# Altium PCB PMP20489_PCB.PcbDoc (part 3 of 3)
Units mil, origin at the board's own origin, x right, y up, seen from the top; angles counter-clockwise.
Board outline 4000 x 6000 mil, 8 copper layers (Top Layer, Signal Layer 1, Signal Layer 2, Signal Layer 3, Signal Layer 4, Signal Layer 5, Signal Layer 6, Bottom Layer), stack 63 mil thick; 331 components, 128 nets, 876 pads, 1027 vias.
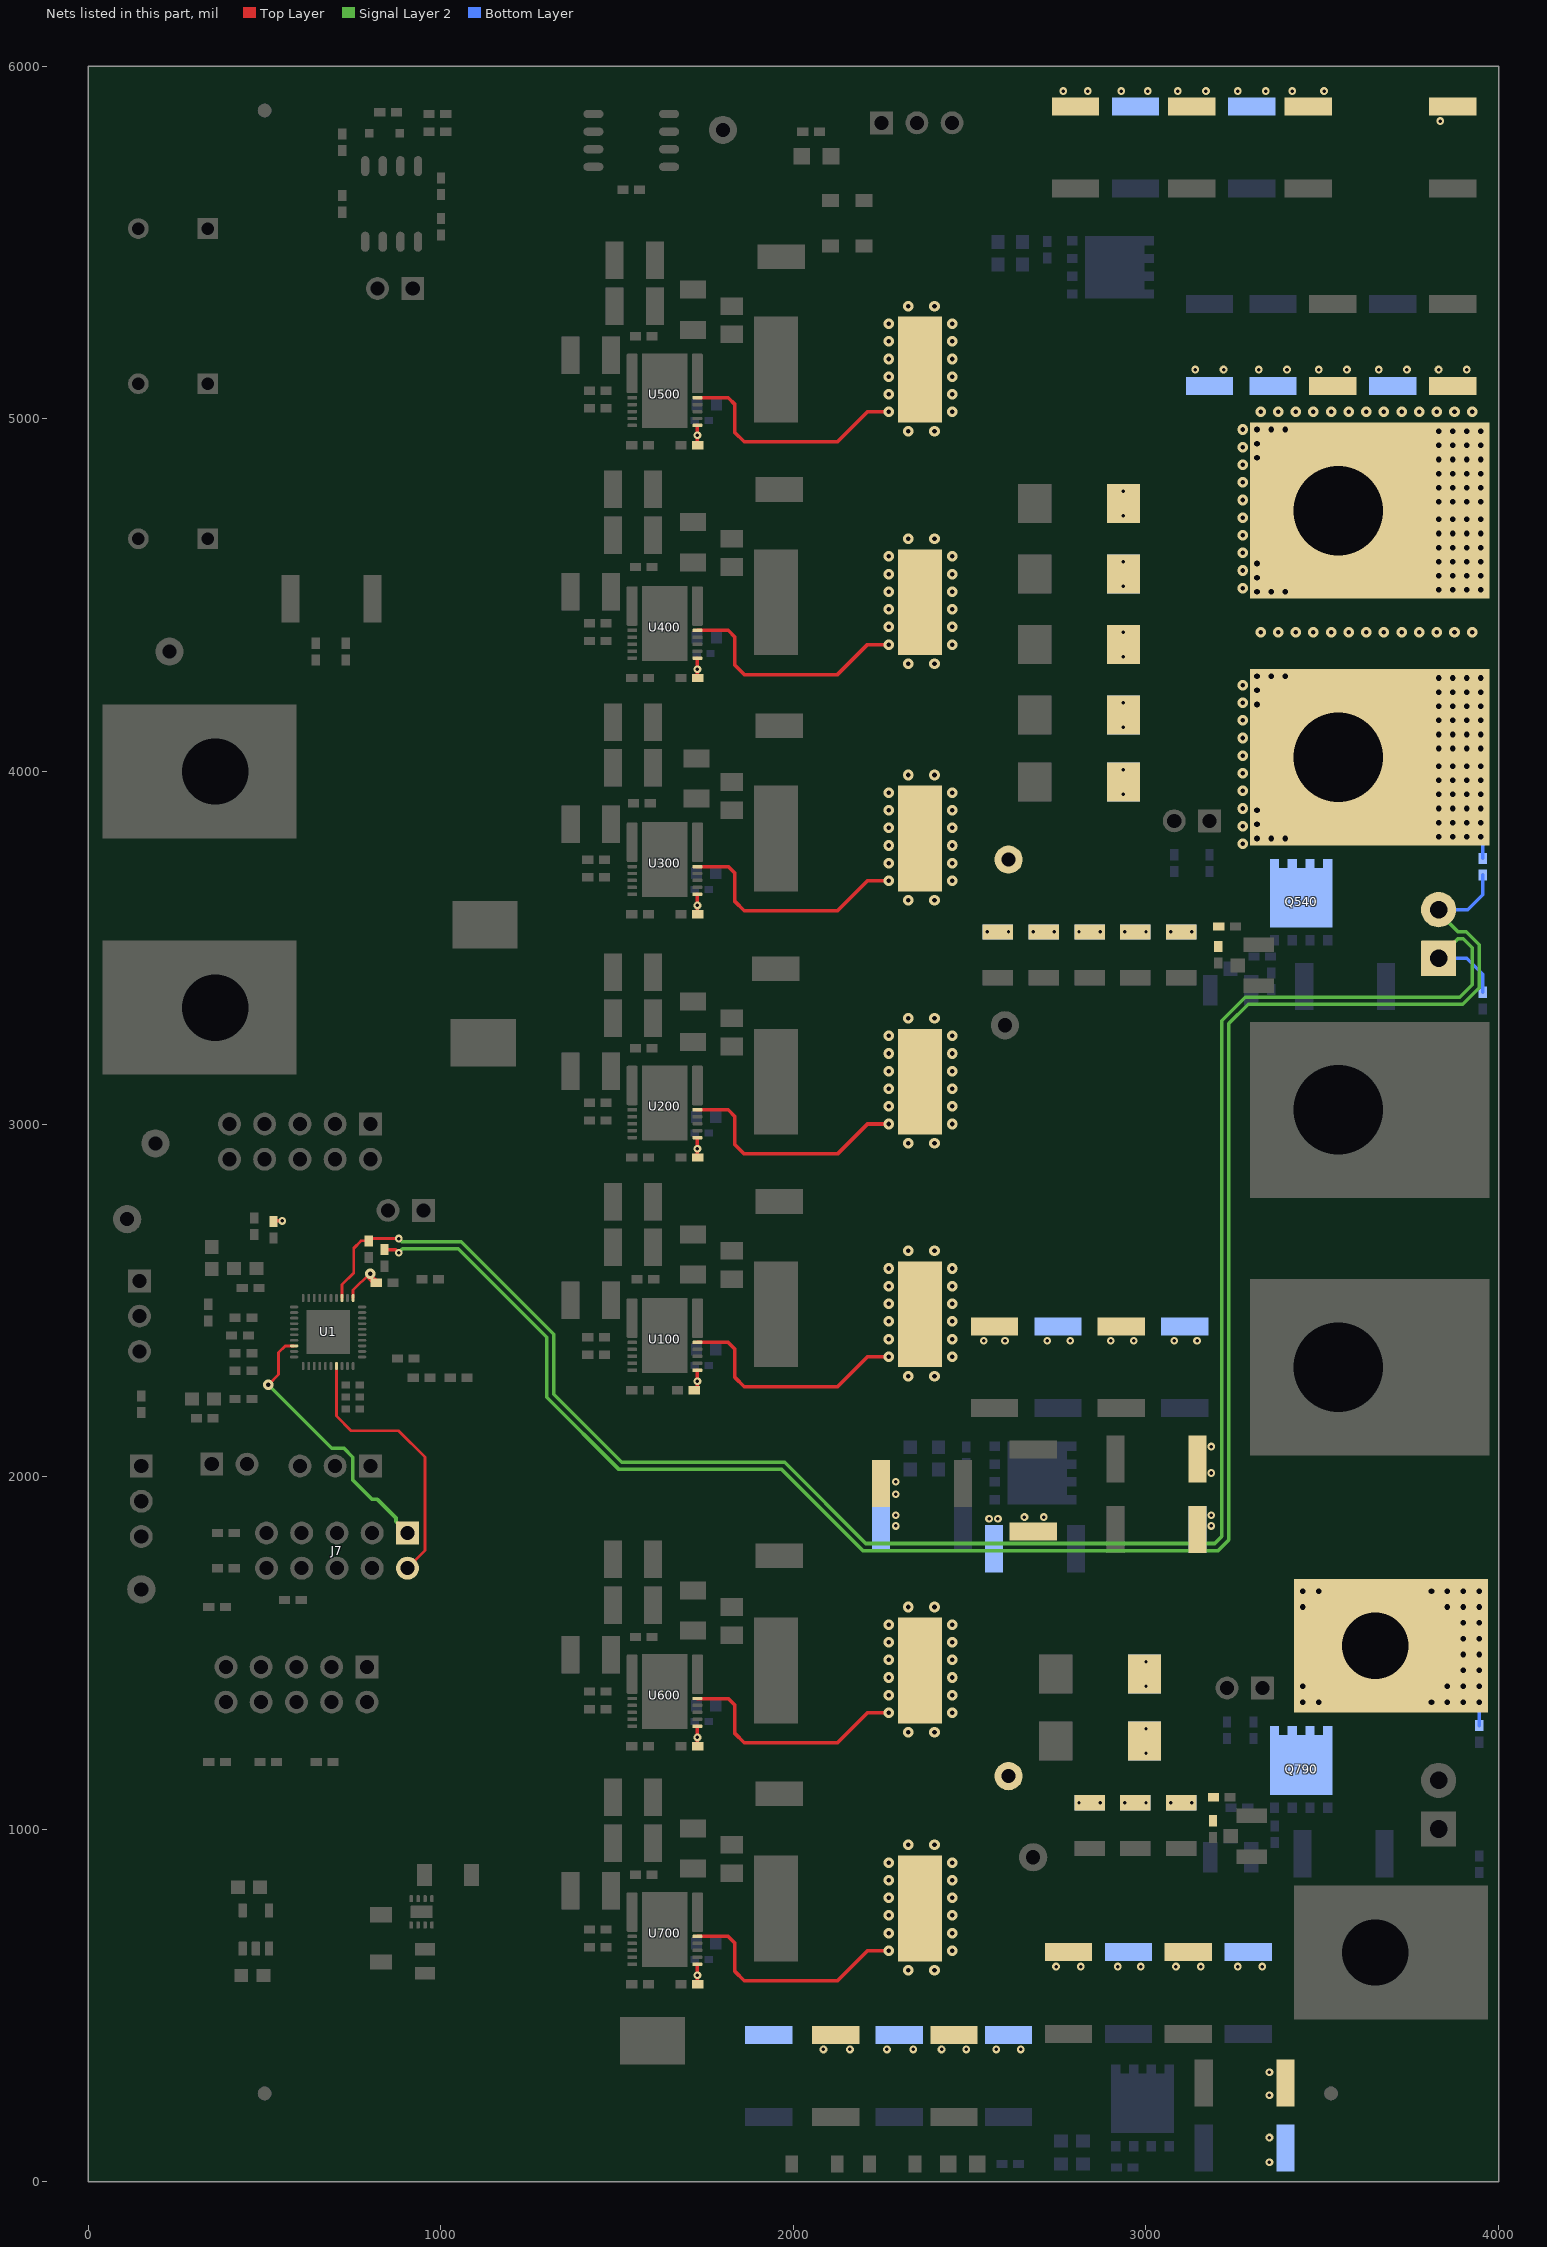
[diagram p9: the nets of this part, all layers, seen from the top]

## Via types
v1: diameter 32, hole 16, Top Layer to Bottom Layer, 344 vias
v2: diameter 22, hole 10, Top Layer to Bottom Layer, tented both sides, 216 vias
v3: diameter 30, hole 13, Top Layer to Bottom Layer, tented both sides, 211 vias
v4: diameter 22, hole 9.7, Top Layer to Bottom Layer, 144 vias
v5: diameter 19.68, hole 7.87, Top Layer to Bottom Layer, 112 vias

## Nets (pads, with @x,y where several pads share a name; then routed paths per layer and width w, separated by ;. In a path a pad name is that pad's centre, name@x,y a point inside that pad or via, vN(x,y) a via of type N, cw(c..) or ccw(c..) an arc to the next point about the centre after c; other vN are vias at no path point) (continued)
VOUT: C21.1 C22.1 C23.1 C24.1 C25.1 C26.1 C27.1 C28.1 C29.1 C30.1 C31.1 C32.1 C33.1 C34.1 C35.1 C36.1 C37.1 C38.1 C39.1 C40.1 C77.1 J15.1 J16.1 L100.2 L200.2 L300.2 L400.2 L500.2 Q540.5 Q540.6 Q540.7 Q540.8 Q540.9 R71.2 R77.2 R505.2 R506.2 R507.2 R508.2 R509.2 R511.2 R512.2 R514.2 R515.2 R525.2 R526.2 R527.2 R528.2 R529.2 R530.2 R531.2 R532.2 R533.2 R534.2 R535.2 R550.2 R553.2 U100.5 U200.5 U300.5 U400.5 U500.5 Vout.1 | length 3468.7
  Top Layer w10: U100.5@1727.52,2380.31 1814.69,2380.31 1834,2361 1834,2281 1860,2255 2125,2255 2210,2340 v3@2275,2340 ; U200.5@1727.52,3040.31 1814.69,3040.31 1834,3021 1834,2941 1860,2915 2125,2915 2210,3000 v3@2275,3000 ; U300.5@1727.52,3730.31 1814.69,3730.31 1834,3711 1834,3631 1860,3605 2125,3605 2210,3690 v3@2275,3690 ; U400.5@1727.52,4400.31 1814.69,4400.31 1834,4381 1834,4301 1860,4275 2125,4275 2210,4360 v3@2275,4360 ; U500.5@1727.52,5060.31 1814.69,5060.31 1834,5041 1834,4961 1860,4935 2125,4935 2210,5020 v3@2275,5020
  Bottom Layer w10: R71.2@3955,3753.62 J16.1@3955,3815
  other v1: 3315,3810 3355,3810 3395,3810 3830,3815 3870,3815 3910,3815 3950,3815 3315,3850 3830,3855 3870,3855 3910,3855 3950,3855 3315,3890 3830,3895 3870,3895 3910,3895 3950,3895 3830,3935 3870,3935 3910,3935 3950,3935 3830,3975 3870,3975 3910,3975 3950,3975 3830,4015 3870,4015 3910,4015 3950,4015 3830,4065 3870,4065 3910,4065 3950,4065 3830,4105 3870,4105 3910,4105 3950,4105 3830,4145 3870,4145 3910,4145 3950,4145 3830,4185 3870,4185 3910,4185 3950,4185 3315,4190 3830,4225 3870,4225 3910,4225 3950,4225 3315,4230 3830,4265 3870,4265 3910,4265 3950,4265 3315,4270 3355,4270 3395,4270 3315,4510 3355,4510 3395,4510 3830,4515 3870,4515 3910,4515 3950,4515 3315,4550 3830,4555 3870,4555 3910,4555 3950,4555 3315,4590 3830,4595 3870,4595 3910,4595 3950,4595 3830,4635 3870,4635 3910,4635 3950,4635 3830,4675 3870,4675 3910,4675 3950,4675 3830,4715 3870,4715 3910,4715 3950,4715 3830,4765 3870,4765 3910,4765 3950,4765 3830,4805 3870,4805 3910,4805 3950,4805 3830,4845 3870,4845 3910,4845 3950,4845 3830,4885 3870,4885 3910,4885 3950,4885 3315,4890 3830,4925 3870,4925 3910,4925 3950,4925 3315,4930 3830,4965 3870,4965 3910,4965 3950,4965 3315,4970 3355,4970 3395,4970
  other v2: 2290,1860 3185,1860 2555,1880 2580,1880 2655,1885 2710,1885 2290,1890 3185,1890 2290,1950 2290,1985 3185,2010 3185,2085 2540,2385 2600,2385 2720,2385 2785,2385 2900,2385 2965,2385 3080,2385 3145,2385 3140,5140 3220,5140 3320,5140 3400,5140 3490,5140 3570,5140 3660,5140 3740,5140 3830,5140 3910,5140 3835,5845 2765,5930 2835,5930 2930,5930 3005,5930 3090,5930 3170,5930 3260,5930 3340,5930 3415,5930 3505,5930
  other v3: 2325,2285 2400,2285 2270,2340 2450,2340 2270,2390 2450,2390 2270,2440 2450,2440 2270,2490 2450,2490 2270,2540 2450,2540 2270,2590 2450,2590 2325,2640 2400,2640 2325,2945 2400,2945 2270,3000 2450,3000 2270,3050 2450,3050 2270,3100 2450,3100 2270,3150 2450,3150 2270,3200 2450,3200 2270,3250 2450,3250 2325,3300 2400,3300 2325,3635 2400,3635 2270,3690 2450,3690 2270,3740 2450,3740 2270,3790 2450,3790 3275,3795 2270,3840 2450,3840 3275,3845 2270,3890 2450,3890 3275,3895 2270,3940 2450,3940 3275,3945 2325,3990 2400,3990 3275,3995 3275,4045 3275,4095 3275,4145 3275,4195 3275,4245 2325,4305 2400,4305 2270,4360 2450,4360 3325,4395 3375,4395 3425,4395 3475,4395 3525,4395 3575,4395 3625,4395 3675,4395 3725,4395 3775,4395 3825,4395 3875,4395 3925,4395 2270,4410 2450,4410 2270,4460 2450,4460 2270,4510 2450,4510 3275,4520 2270,4560 2450,4560 3275,4570 2270,4610 2450,4610 3275,4620 2325,4660 2400,4660 3275,4670 3275,4720 3275,4770 3275,4820 3275,4870 3275,4920 2325,4965 2400,4965 3275,4970 2270,5020 2450,5020 3325,5020 3375,5020 3425,5020 3475,5020 3525,5020 3575,5020 3625,5020 3675,5020 3725,5020 3775,5020 3825,5020 3875,5020 3925,5020 2270,5070 2450,5070 2270,5120 2450,5120 2270,5170 2450,5170 2270,5220 2450,5220 2270,5270 2450,5270 2325,5320 2400,5320
  other v4: 2550,3545 2610,3545 2680,3545 2740,3545 2810,3545 2870,3545 2940,3545 3000,3545 3070,3545 3130,3545 2935,3935 2935,4005 2935,4125 2935,4195 2935,4325 2935,4395 2935,4525 2935,4595 2935,4725 2935,4795
VOUTB: C721.1 C722.1 C723.1 C724.1 C725.1 C726.1 C727.1 C728.1 C729.1 C730.1 C777.1 J701.1 L600.2 L700.2 Q790.5 Q790.6 Q790.7 Q790.8 Q790.9 R771.2 R775.2 R776.2 R777.2 R778.2 R780.2 R781.2 R782.2 R783.2 R784.2 R785.2 R786.2 R787.2 U600.5 U700.5 VoutB.1 | length 1429.3
  Top Layer w10: U700.5@1727.52,695.31 1814.69,695.31 1834,676 1834,596 1860,570 2125,570 2210,655 v3@2275,655 ; U600.5@1727.52,1370.31 1814.69,1370.31 1834,1351 1834,1271 1860,1245 2125,1245 2210,1330 v3@2275,1330
  Bottom Layer w10: R771.2@3945,1293.62 v1(3945,1360)
  other v1: 3445,1360 3490,1360 3810,1360 3855,1360 3900,1360 3445,1405 3855,1405 3900,1405 3945,1405 3900,1450 3945,1450 3900,1495 3945,1495 3900,1540 3945,1540 3900,1585 3945,1585 3445,1630 3855,1630 3900,1630 3945,1630 3445,1675 3490,1675 3810,1675 3855,1675 3900,1675 3945,1675
  other v2: 3350,55 3350,125 3350,245 3350,310 2085,375 2160,375 2265,375 2340,375 2420,375 2490,375 2575,375 2645,375 2745,610 2815,610 2920,610 2985,610 3085,610 3155,610 3260,610 3330,610
  other v3: 2325,600 2400,600 2270,655 2450,655 2270,705 2450,705 2270,755 2450,755 2270,805 2450,805 2270,855 2450,855 2270,905 2450,905 2325,955 2400,955 2325,1275 2400,1275 2270,1330 2450,1330 2270,1380 2450,1380 2270,1430 2450,1430 2270,1480 2450,1480 2270,1530 2450,1530 2270,1580 2450,1580 2325,1630 2400,1630
  other v4: 2810,1075 2870,1075 2940,1075 3000,1075 3070,1075 3130,1075 3000,1215 3000,1285 3000,1405 3000,1475
VR_FAULT#: J7.2 U1.27 | length 784.5
  Top Layer w7.87: U1.27@703.62,2313.54 703.62,2264.49 703.69,2264.42 703.69,2171.31 745,2130 880,2130
  Top Layer w8: 880,2130 955,2055 955,1790 J7.2@900,1735
VR_HOT#: J7.1 U1.18 | length 768.7
  Top Layer w7.87: v3(510,2260) 539.25,2289.25 539.25,2351.52 558.36,2370.63 U1.18@583.54,2370.63
  Signal Layer 2 w10: v3(510,2260) 690,2080 725,2080 750,2055 750,1990 805,1935 820,1935 872.5,1882.5 872.5,1872.5 J7.1@905,1840
VREF: C6.1 C112.1 C212.1 C312.1 C412.1 C512.1 C612.1 C712.1 R4.2 U1.1 U100.1 U200.1 U300.1 U400.1 U500.1 U600.1 U700.1 | length 546.9
  Top Layer w7.87: U1.1@750.87,2506.46 750.87,2528.59 v3@798.64,2576.36
  Top Layer w10: R4.2@525,2723.62 526.38,2725 v2(550,2725) ; U700.1@1727.52,616.55 v2(1727.52,585) 1727.52,561.1 C712.1@1728.62,560 ; U600.1@1727.52,1291.55 v2(1727.52,1260) 1727.52,1236.1 C612.1@1728.62,1235 ; U100.1@1727.52,2301.55 v2(1727.52,2270) 1727.52,2246.1 C112.1@1728.62,2245 ; U200.1@1727.52,2961.55 v2(1727.52,2930) 1727.52,2906.1 C212.1@1728.62,2905 ; U300.1@1727.52,3651.55 v2(1727.52,3620) 1727.52,3596.1 C312.1@1728.62,3595 ; U400.1@1727.52,4321.55 v2(1727.52,4290) 1727.52,4266.1 C412.1@1728.62,4265 ; U500.1@1727.52,4981.55 1727.52,4926.1 C512.1@1728.62,4925
  Top Layer w20: v3(800,2575) 800,2565 815,2550 C6.1@816.38,2550
  other v2: 1727.52,4953.83
VSN: C60.2 J14.1 R72.1 U1.3 | length 5738.4
  Top Layer w7.87: U1.3@719.37,2506.46 719.37,2544.37 752.6,2577.6 752.6,2647.6 773.62,2668.62 788.62,2668.62 795,2675 v2(880,2675)
  Signal Layer 2 w10: v2(880,2675) 888.9,2666.1 1057.18,2666.1 1320,2403.28 1320,2233.28 1513.28,2040 1975,2040 2205,1810 3195,1810 3215,1830 3215,3293.28 3281.72,3360 3890,3360 3925,3395 3925,3500 3900,3525 3885,3525 J14.1@3830,3470
  Bottom Layer w10: J14.1@3830,3470 3910,3470 3955,3425 R72.1@3955,3373.62
VSP: J14.2 R62.2 R71.1 | length 5568.3
  Top Layer w10: R62.2@840,2643.62 871.38,2643.62 v2(880,2635)
  Signal Layer 2 w10: v2(880,2635) 891.1,2646.1 1048.9,2646.1 1300,2395 1300,2225 1505,2020 1966.29,2020 2196.29,1790 3205,1790 3235,1820 3235,3285 3290,3340 3898.28,3340 3945,3386.72 3945,3508.28 3908.28,3545 3885,3545 3830,3600 J14.2@3830,3608
  Bottom Layer w10: J14.2@3830,3608 3913,3608 3955,3650 R71.1@3955,3706.38
pads on no net: FID1.1 FID2.1 FID3.1 FID4.1 FID5.1 FID6.1 H1.0 H2.0 H3.0 H4.0 J6.1 J6.2 J6.3 J6.5 U100.13@1603.31,2322.05 U100.13@1603.31,2374.02 U100.13@1603.31,2425.98 U100.13@1603.31,2477.95 U100.13@1666.69,2322.05 U100.13@1666.69,2374.02 U100.13@1666.69,2425.98 U100.13@1666.69,2477.95 U200.13@1603.31,2982.05 U200.13@1603.31,3034.02 U200.13@1603.31,3085.98 U200.13@1603.31,3137.95 U200.13@1666.69,2982.05 U200.13@1666.69,3034.02 U200.13@1666.69,3085.98 U200.13@1666.69,3137.95 U300.13@1603.31,3672.05 U300.13@1603.31,3724.02 U300.13@1603.31,3775.98 U300.13@1603.31,3827.95 U300.13@1666.69,3672.05 U300.13@1666.69,3724.02 U300.13@1666.69,3775.98 U300.13@1666.69,3827.95 U400.13@1603.31,4342.05 U400.13@1603.31,4394.02 U400.13@1603.31,4445.98 U400.13@1603.31,4497.95 U400.13@1666.69,4342.05 U400.13@1666.69,4394.02 U400.13@1666.69,4445.98 U400.13@1666.69,4497.95 U500.13@1603.31,5002.05 U500.13@1603.31,5054.02 U500.13@1603.31,5105.98 U500.13@1603.31,5157.95 U500.13@1666.69,5002.05 U500.13@1666.69,5054.02 U500.13@1666.69,5105.98 U500.13@1666.69,5157.95 U600.13@1603.31,1312.05 U600.13@1603.31,1364.02 U600.13@1603.31,1415.98 U600.13@1603.31,1467.95 U600.13@1666.69,1312.05 U600.13@1666.69,1364.02 U600.13@1666.69,1415.98 U600.13@1666.69,1467.95 U700.13@1603.31,637.05 U700.13@1603.31,689.02 U700.13@1603.31,740.98 U700.13@1603.31,792.95 U700.13@1666.69,637.05 U700.13@1666.69,689.02 U700.13@1666.69,740.98 U700.13@1666.69,792.95 U801.1 U801.5 U801.8 U900.8 U901.4

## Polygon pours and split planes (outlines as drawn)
VOUTB on Top Layer "Top Layer-No Net" (solid, remove dead copper, pour order 6): 2220,1650 2220,1730 3305,1730 3990,1730 3985,1725 3985,855 3420,855 3420,25 3195,25 2950,270 2220,270
VIN on Top Layer "Top Layer-VIN" (solid, remove dead copper, pour order 2): 780,4640 1005,4640 1005,4345 780,4345
VOUT on Top Layer "Top Layer-VOUT" (solid, remove dead copper, pour order 4): 3975,5975 2750,5975 2220,5445 2220,1755 3267.87,1755 3267.87,3320 3975,3320
GND on Top Layer "Top Layer-No Net" (solid, remove dead copper, pour order 50): 1700,5975 1700,25 25,25 25,3725 1025,3725 1025,4675 650,4675 650,5975
5V on Signal Layer 4 "Top Layer-No Net" (solid, remove dead copper, pour order 12): 1795,5465 1795,580 1770,555 415,555 415,500 487.5,427.5 675,427.5 1847.5,427.5 1935,515 1935,5495 1710,5720 710,5720 710,5597.5 1662.5,5597.5
VIN on Signal Layer 4 "Top Layer-No Net" (solid, remove dead copper, pour order 8): 740,4640 740,5030 740,5090 1000,5350 1170,5520 1550,5520 1550,765 1000,765 1000,1680 1000,3310 740,3570
VOUT on Signal Layer 4 "Top Layer-VOUT" (solid, remove dead copper, pour order 24): 3970,5970 2745,5970 2220,5445 2220,1755 3267.87,1755 3267.87,3371.37 3970,3370
VOUTB on Signal Layer 4 "Top Layer-No Net" (solid, remove dead copper, pour order 30): 2220,1650 2220,1730 3305,1730 3990,1730 3985,1725 3985,855 3420,855 3420,25 3195,25 2950,270 2220,270
VIN on Signal Layer 6 "Top Layer-No Net" (solid, remove dead copper, pour order 10): 865,4680 1005,4820 1495,4820 1490,1440 1415,1440 1187.5,1667.5 1187.5,3122.5 865,3445
VREF on Signal Layer 6 "vref" (solid, remove dead copper, pour order 16): 1715,4740 1715,1270 1695,1250 1670,1250 1480,1250 1280,1450 1140,1590 1140,1915 1140,3000 1140,3105 1025,3105 340,3105 300,3065 295,3060 295,3010 295,2865 520,2640 600,2560 650,2510 730,2510 760,2480 760,2345 710,2295 710,2145 760,2095 920,2095 997.5,2017.5 997.5,1497.5 1352.5,1142.5 1610,1142.5 1715,1037.5 1715,565 1755,565 1755,610 1825,715 1965,855 1967.5,4740 1731.25,4976.25 1695,4955 905,4955 715,4765 715,3330 715,3225 595,3105 1140,3105 1140,3110 847.5,3402.5 847.5,4702.5 980,4835 1620,4835
VOUT on Signal Layer 6 "Top Layer-VOUT" (solid, remove dead copper, pour order 26): 3970,5970 2665,5970 2665,5385 2220,5385 2220,1755 3267.87,1755 3267.87,3371.37 3970,3370
VOUTB on Signal Layer 6 "Top Layer-No Net" (solid, remove dead copper, pour order 32): 2220,1650 2220,1730 3305,1730 3990,1730 3985,1725 3985,855 3420,855 3420,25 3195,25 2950,270 2220,270
NetQ520_5 on Bottom Layer "Top Layer-No Net" (solid, remove dead copper, pour order 14): 2395,1975 2395,1780 2395,1735 2450,1680 2940,1680 2995,1735 2995,1950 3180,2135 3180,2260 2500,2260 2500,2055
NetQ500_5 on Bottom Layer "Top Layer-No Net" (solid, remove dead copper, pour order 18): 2825,5725 3535,5725 3935,5725 3935,5420 3935,5260 3680,5260 2825,5260
NetQ770_5 on Bottom Layer "Top Layer-No Net" (solid, remove dead copper, pour order 20): 1860,330 1865,325 2660,325 2700,325 2705,330 2705,450 3360,450 3360,390 3320,350 3235,265 3235,25 3100,25 3100,100 3100,135 2940,135 2885,135 2865,155 2860,160 2715,160 1860,160
NetC790_1 on Bottom Layer "Top Layer-No Net" (solid, remove dead copper, pour order 34): 3400,1080 3540,1080 3645,1080 3675,1050 3700,1025 3715,1010 3715,985 3715,860 3650,860 3650,945 3565,1030 3515,1030 3400,1030
VOUTB on Bottom Layer "Top Layer-No Net" (solid, remove dead copper, pour order 36): 3350,1325 3395,1370 3395,1405 3395,1730 3975,1730 3975,1330 3925,1330 3695,1100 3350,1100
VOUT on Bottom Layer "Top Layer-No Net" (solid, remove dead copper, pour order 38): 3257.5,3652.5 3257.5,3915 2890,3915 2890,4525 2890,5155 3257.5,5155 3980,5155 3980,4290 3980,3790 3920,3790 3690,3560 3350,3560
NetC540_1 on Bottom Layer "Top Layer-No Net" (solid, remove dead copper, pour order 40): 3405,3540 3545,3540 3650,3540 3680,3510 3705,3485 3720,3470 3720,3445 3720,3320 3655,3320 3655,3405 3570,3490 3520,3490 3405,3490
GND on Bottom Layer "Top Layer-No Net" (solid, remove dead copper, pour order 48): 25,5975 3975,5975 3975,25 25,25
VOUT on Signal Layer 2 "Top Layer-VOUT" (solid, remove dead copper, pour order 22): 3970,5970 2745,5970 2220,5445 2220,1755 3267.87,1755 3267.87,3371.37 3970,3370
VOUTB on Signal Layer 2 "Top Layer-No Net" (solid, remove dead copper, pour order 28): 2220,1650 2220,1730 3305,1730 3990,1730 3985,1725 3985,855 3420,855 3420,600 3090,270 2950,270 2220,270
GND on Signal Layer 1 "Top Layer-No Net" (solid, remove dead copper, pour order 42): 25,5975 3975,5975 3975,25 25,25
GND on Signal Layer 3 "Top Layer-No Net" (solid, remove dead copper, pour order 44): 25,5975 3975,5975 3975,25 25,25
GND on Signal Layer 5 "Top Layer-No Net" (solid, remove dead copper, pour order 46): 25,5975 3975,5975 3975,25 25,25

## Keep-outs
Keep-Out Layer:
  lines w20: -10,0 ccw(c0,0) 0,-10 ; -10,0 ccw(c0,0) 0,-10 ; -10,0 -10,6000 ; -10,6000 cw(c0,6000) 0,6010 ; -10,6000 cw(c0,6000) 0,6010 ; 0,-10 4000,-10 ; 0,6010 4000,6010 ; 4000,-10 ccw(c4000,0) 4010,0 ; 4000,-10 ccw(c4000,0) 4010,0 ; 4000,6010 cw(c4000,6000) 4010,6000 ; 4000,6010 cw(c4000,6000) 4010,6000 ; 4010,0 4010,6000
  text ".Layer_Name" at 577,-858.49 h60

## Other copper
Top Layer:
  rectangle net VIN: 1000,3480 1250,3650
  rectangle net VIN_P: 190,3810 600,5630
  rectangle net VIN: 930,835 1030,900
  rectangle net VIN: 930,795 960,840
  rectangle net 5V: 800,525 860,645
  rectangle net 5V: 800,575 985,625
  rectangle net VOUTB: 2050,360 2355,440
  rectangle net NetQ520_5: 2895,2170 2965,2245
  rectangle net NetQ520_5: 2890,2010 2965,2090
  rectangle net NetQ520_5: 2540,2170 2610,2245
  rectangle net NetQ520_5: 2645,2050 2720,2125
  rectangle net NetQ520_5: 2430,1855 2505,1970
  rectangle net NetQ500_5: 3820,5270 3920,5350
  rectangle net NetQ500_5: 3480,5270 3580,5350
  region net NetQ500_5: 3510,5710 3410,5710 3410,5630 3510,5630
  region net NetQ500_5: 3920,5710 3820,5710 3820,5630 3920,5630
  region net NetQ500_5: 3180,5710 3080,5710 3080,5630 3180,5630
  rectangle net NetQ500_5: 2825,5606.03 2866.67,5705
  rectangle net NetQ770_5: 2075,160 2165,240
  rectangle net NetQ770_5: 2415,160 2500,240
  rectangle net NetQ770_5: 3140,240 3220,320
  rectangle net NetQ770_5: 2735,360 2825,440
  rectangle net NetQ770_5: 3045,360 3095,445
  rectangle net VIN_P: 30,3810 230,4615
  rectangle net NetQ520_5: 2890,1850 2965,1900
  region net VIN: 1560,5515 1560,5075 1520,5075 1485,5110 1430,5110 1430,5515
  region net NetC513_1: 1710,5075 1845,5075 1890,5030 1890,4990 2015,4990 2015,5495 1887,5495 1887,5287 1865,5265 1790,5265 1790,5225 1765,5200 1710,5200
  region net NetC513_2: 1855,5295 1790,5295 1745,5340 1680,5340 1680,5395 1755,5395 1805,5345 1855,5345
  region net NetC313_2: 1855,3965 1790,3965 1745,4010 1680,4010 1680,4065 1755,4065 1805,4015 1855,4015
  region net NetC313_1: 1710,3745 1845,3745 1890,3700 1890,3660 2015,3660 2015,4165 1887,4165 1887,3957 1865,3935 1790,3935 1790,3895 1765,3870 1710,3870
  region net VIN: 1560,4195 1560,3745 1520,3745 1485,3780 1430,3780 1430,4195
  region net NetC413_2: 1855,4635 1790,4635 1745,4680 1680,4680 1680,4735 1755,4735 1805,4685 1855,4685
  region net VIN: 1560,4855 1560,4415 1520,4415 1485,4450 1430,4450 1430,4855
  region net NetC213_2: 1855,3275 1790,3275 1745,3320 1680,3320 1680,3375 1755,3375 1805,3325 1855,3325
  region net NetC213_1: 1710,3055 1845,3055 1890,3010 1890,2970 2015,2970 2015,3475 1887,3475 1887,3267 1865,3245 1790,3245 1790,3205 1765,3180 1710,3180
  region net VIN: 1560,3495 1560,3055 1520,3055 1485,3090 1430,3090 1430,3495
  region net NetC113_2: 1855,2615 1790,2615 1745,2660 1680,2660 1680,2715 1755,2715 1805,2665 1855,2665
  region net NetC113_1: 1710,2395 1845,2395 1890,2350 1890,2310 2015,2310 2015,2815 1887,2815 1887,2607 1865,2585 1790,2585 1790,2545 1765,2520 1710,2520
  region net VIN: 1560,2835 1560,2395 1520,2395 1485,2430 1430,2430 1430,2835
  region net NetC613_2: 1855,1605 1790,1605 1745,1650 1680,1650 1680,1705 1755,1705 1805,1655 1855,1655
  region net NetC613_1: 1710,1385 1845,1385 1890,1340 1890,1300 2015,1300 2015,1805 1887,1805 1887,1597 1865,1575 1790,1575 1790,1535 1765,1510 1710,1510
  region net VIN: 1560,1825 1560,1385 1520,1385 1485,1420 1430,1420 1430,1825
  region net NetC713_2: 1855,930 1790,930 1745,975 1680,975 1680,1030 1755,1030 1805,980 1855,980
  region net NetC713_1: 1710,710 1845,710 1890,665 1890,625 2015,625 2015,1130 1887,1130 1887,922 1865,900 1790,900 1790,860 1765,835 1710,835
  region net VIN: 1560,1150 1560,710 1520,710 1485,745 1430,745 1430,1150
  region net NetC413_1: 1710,4415 1845,4415 1890,4370 1890,4330 2015,4330 2015,4835 1887,4835 1887,4627 1865,4605 1790,4605 1790,4565 1765,4540 1710,4540
  text ".Layer_Name" at 577,-858.49 h60
Signal Layer 1:
  text ".Layer_Name" at 577,-858.49 h60
Signal Layer 2:
  rectangle net GND: 1565,2290 1705,2510
  rectangle net GND: 1565,1280 1705,1500
  rectangle net GND: 1565,605 1705,825
  rectangle net GND: 1565,2950 1705,3170
  rectangle net GND: 1565,3640 1705,3860
  rectangle net GND: 1565,4310 1705,4530
  rectangle net GND: 1565,4970 1705,5190
  rectangle net VOUTB: 2070,360 2280,440
  rectangle net GND: 615,2345 745,2475
  text ".Layer_Name" at 577,-858.49 h60
Signal Layer 3:
  text ".Layer_Name" at 577,-858.49 h60
Signal Layer 4:
  rectangle net GND: 1565,605 1705,5520
  rectangle net GND: 615,2345 745,2475
  rectangle net VIN_P: 190,3810 600,5630
  rectangle net VOUTB: 2075,360 2275,440
  rectangle net VIN_P: 30,3810 230,4615
  text ".Layer_Name" at 577,-858.49 h60
Signal Layer 5:
  text ".Layer_Name" at 577,-858.49 h60
Signal Layer 6:
  rectangle net VREF: 603,3100.93 1140,3113
  rectangle net GND: 1565,4970 1705,5190
  rectangle net GND: 1565,4310 1705,4530
  rectangle net GND: 1565,3640 1705,3860
  rectangle net GND: 1565,2950 1705,3170
  rectangle net GND: 1565,605 1705,825
  rectangle net GND: 1565,1280 1705,1500
  rectangle net GND: 1565,2290 1705,2510
  rectangle net VIN_P: 190,3810 600,5630
  rectangle net VIN_P: 30,3810 220,4615
  rectangle net GND: 615,2345 745,2475
  text ".Layer_Name" at 577,-858.49 h60
Bottom Layer:
  rectangle net VOUTB: 3340,40 3420,140
  rectangle net VOUTB: 1865,360 2675,440
  rectangle net VOUTB: 3240,600 3345,675
  rectangle net VOUTB: 2900,600 3005,675
  region net VOUT: 2300,1815 2300,1920 2225,1920 2225,1815
  region net VOUT: 2595,1730 2595,1895 2545,1895 2545,1730
  region net VOUT: 3197.28,1800 3197.28,1905 3122.28,1905 3122.28,1800
  rectangle net VOUT: 3060,2375 3165,2450
  rectangle net VOUT: 2700,2375 2805,2450
  rectangle net VOUT: 3235,5870 3365,5940
  rectangle net VOUT: 2905,5875 3035,5940
  rectangle net VOUT: 3115,5075 3245,5150
  rectangle net VOUT: 3295,5075 3425,5150
  rectangle net VOUT: 3635,5075 3765,5150
  rectangle net GND: 2460,1935 2585,2050
  rectangle net GND: 2520,1910 2585,1940
  rectangle net GND: 2950,25 3080,115
  rectangle net GND: 2705,5330 2805,5470
  text ".Layer_Name" at 577,-858.49 h60

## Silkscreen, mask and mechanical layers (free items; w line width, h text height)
Top Overlay:
  region: 1650,275 1350,275 1350,175 1650,175
  text "Main   CH2" at 2195,5730 h72.83
  text "dyn load select" at 2145,5675 h72.83
  text "dyn load" at 750,5260 h72.83
  text "clock enable" at 750,5170 h72.83
  text "Main Vout" at 3250,4060 h200 r90
  text "sig gen" at 3030,4010 h72.83
  text "gnd +" at 3050,3940 h72.83
  text "VIN" at 760,3830 h200 r90
  text "Vsense" at 3040,3280 h72.83
  text "RTN" at 760,3160 h200 r90
  text "main ch" at 920,2990 h72.83
  text "phase sel" at 900,2880 h72.83
  text "EN ch2 DIS" at 265,2285 h72.83 r90
  text "Main Vout Rtn" at 3230,2130 h150 r90
  text "reset" at 330,2100 h72.83
  text "main EN DIS" at 525,2100 h72.83
  text "ext bias 3.3V" at 260,1760 h72.83 r90
  text "CH2+" at 3390,1730 h160
  text "SVID signals" at 980,1715 h72.83
  text "sig gen" at 3185,1550 h72.83
  text "gnd +" at 3200,1475 h72.83
  text "PMBus Communications" at 250,1060 h72.83
  text "vsense" at 3230,850 h72.83
  text "RTN" at 3405,510 h160 r90
  text "3.3V reg" at 365.31,480 h72.83
  text "5V reg" at 840,470 h72.83
  text "'.PRJ_Number'.PCB_Rev-" at 725,250 h108.27
  text ".Layer_Name" at 577,-858.49 h60
  text "Main Vout Rtn" at 5360,-6490 h100 r90
Bottom Overlay:
  text "Isense" at 3240,3240 h72.83
  text "Isense" at 3330,760 h72.83
  text ".Layer_Name" at 577,-858.49 h60
Top Paste:
  text ".Layer_Name" at 577,-858.49 h60
Bottom Paste:
  text ".Layer_Name" at 577,-858.49 h60
Top Solder:
  text ".Layer_Name" at 577,-858.49 h60
  text ".Layer_Name" at 577,-858.49 h60
Bottom Solder:
  text ".Layer_Name" at 577,-858.49 h60
Drill Guide:
  text ".Layer_Name" at 577,-858.49 h60
M1 Board Outline:
  the board outline again, w10
M2 Board Dimensions:
  rectangle: 0,-275 125,-150
  rectangle: 125,-400 500,-275
  lines w7: 0,-275 1000,-275 ; 125,-400 125,-150 ; 250,-400 250,-150 ; 500,-400 500,-150 ; 750,-400 750,-150 ; 0,-400 1000,-400 1000,-150 0,-150 0,-400
  text ".Layer_Name" at 577,-858.49 h60
M3 3D STEP Top:
  text ".Layer_Name" at 577,-858.49 h60
M4 3D STEP Bottom:
  text ".Layer_Name" at 577,-858.49 h60
M5 Assembly Top:
  lines w10: -292,-930.17 6308,-930.17 ; -292,-726.83 6310,-726.83 ; -292,-523.5 -292,-1133.5 3713,-1133.5 6310,-1133.5 6310,-523.5 -291.5,-523.5 -291.5,-1133.5 1284,-1133.5 ; 2173,-1133.5 2173,-523.5 ; 3440,-726.83 3440,-523.5 ; 4280,-726.83 4280,-523.5 ; 4902,-1140 4902,-937.17
  text "COMPONENTS MARKED 'DNP' SHOULD NOT BE POPULATED." at 1153.5,-318.5 h60
  text "ASSEMBLY VARIANT:" at 1153,-434 h60
  text ".VariantName" at 2189,-434 h60
  text "PCB VIEWED FROM TOP SIDE" at -228.5,-655.67 h60
  text "BOARD #:" at 2248,-655.67 h60
  text ".PRJ_Number" at 2793.5,-655.67 h60
  text "REV:" at 3638,-655.67 h60
  text ".PCB_Rev" at 3929.5,-655.67 h60
  text "SVN REV:" at 4476,-655.67 h60
  text ".VersionControl_RevNumber" at 4982,-655.67 h60
  text "TID #:" at 2248,-859 h60
  text ".TID" at 2793.5,-859 h60
  text "PLOT NAME =" at -228.5,-1064.34 h60
  text ".plot_File_Name" at 577,-1064.34 h60
  text "GENERATED    :" at 2250,-1064.34 h60
  text ".Print_Date" at 3119.5,-1064.34 h60
  text ".Print_Time" at 3848.5,-1064.34 h60
  text "TEXAS INSTRUMENTS" at 5113,-1064.34 h60
M6 Assembly Bottom:
  lines w10: -292.5,-727.33 6309.5,-727.33 ; -290.5,-930.67 6309.5,-930.67 ; 1115.5,-1140.5 1115.5,-937.67 ; 1737.5,-727.33 1737.5,-524 ; 2577.5,-727.33 2577.5,-524 ; 3844.5,-1134 3844.5,-524 ; 4733.5,-1134 6309,-1134 6309,-524 -292.5,-524 -292.5,-1134 2304.5,-1134 6309.5,-1134 6309.5,-524
  text "COMPONENTS MARKED 'DNP' SHOULD NOT BE POPULATED." at 6102,-318 h60
  text ".VariantName" at 5058,-434 h60
  text "ASSEMBLY VARIANT:" at 6097,-434 h60
  text ".VersionControl_RevNumber" at 1035.5,-656.17 h60
  text "SVN REV:" at 1541.5,-656.17 h60
  text ".PCB_Rev" at 2088,-656.17 h60
  text "REV:" at 2379.5,-656.17 h60
  text ".PRJ_Number" at 3224,-656.17 h60
  text "BOARD #:" at 3769.5,-656.17 h60
  text "PCB VIEWED FROM BOTTOM SIDE" at 6246,-656.17 h60
  text ".TID" at 3224,-859.5 h60
  text "TID #:" at 3769.5,-859.5 h60
  text "TEXAS INSTRUMENTS" at 904.5,-1064.84 h60
  text ".Print_Time" at 2169,-1064.84 h60
  text ".Print_Date" at 2898,-1064.84 h60
  text "GENERATED    :" at 3767.5,-1064.84 h60
  text ".plot_File_Name" at 5440.5,-1064.84 h60
  text "PLOT NAME =" at 6246,-1064.84 h60
M9 Title Sheet:
  drawing of 57 lines, arcs and shapes, not listed
  text "1" at 739.84,8036.5 h70
  text "2" at 3235.5,8036.5 h70
  text "3" at 5724.84,8036.5 h70
  text "4" at 8231.51,8036.5 h70
  text "5" at 10730.5,8036.5 h70
  text "6" at 13235.5,8036.5 h70
  text "A" at -416.5,6893.5 h70
  text "A" at 14383.5,6893.5 h70
  text "B" at -416.5,4513.5 h70
  text "B" at 14383.5,4513.5 h70
  text "C" at -416.5,2138.5 h70
  text "C" at 14383.5,2138.5 h70
  text "PROJECT TITLE:" at 11343.5,277.5 h45
  text ".PRJ_Title" at 11393.5,144.17 h70
  text "DESIGNED FOR:" at 11343.5,-23.5 h45
  text ".PRJ_Customer" at 11393.5,-163.5 h70
  text "D" at -416.5,-231.5 h70
  text "D" at 14383.5,-231.5 h70
  text "FILE NAME:" at 11343.5,-323.5 h45
  text ".PCB_File_Name_No_Path" at 11393.5,-443.5 h70
  text "Texas Instruments (TI) and/or its licensors do not warrant the accuracy or completeness of this specification" at 6374,-605.34 h45
  text "ENGINEER:" at 11343.5,-613.5 h45
  text "LAYOUT BY:" at 12848.5,-613.5 h45
  text "or any information contained therein. TI and/or its licensors do not warrant that this design will meet" at 6329.01,-718 h45
  text ".PRJ_Engineer" at 11393.5,-768.49 h70
  text ".PCB_Layout" at 12899,-768.49 h70
  text "the specifications, will be suitable for your application or fit for any particular purpose, or will operate in" at 6329.01,-830.67 h45
  text ".Layer_Name" at 577,-858.49 h60
  text "ALTIUM DESIGNER VERSION:" at 12848.5,-923.5 h45
  text "an implementation. TI and/or its licensors do not warrant that the design is production worthy. You should" at 6329.01,-943.33 h45
  text "completely validate and test your design implementation to confirm the system functionality for your application." at 6374,-1056 h45
  text ".print_Scale" at 11393.5,-1056.83 h70
  text ".Application_BuildNumber" at 12899,-1056.83 h70
  text "1" at 739.84,-1263.5 h70
  text "2" at 3235.5,-1263.5 h70
  text "3" at 5724.84,-1263.5 h70
  text "4" at 8231.51,-1263.5 h70
  text "5" at 10730.5,-1263.5 h70
  text "6" at 13235.5,-1263.5 h70
M10 Fab Notes:
  drawing of 173 lines, arcs and shapes, not listed
  text "DESIGN INFORMATION" at 12378.02,6201 h60
  text "MIN. TRACK WIDTH:" at 11733.46,6021 h60
  text "8" at 12829.7,6021 h60
  text "MIL" at 12984.46,6021 h60
  text "MIN. CLEARANCE:" at 11733.46,5889 h60
  text "0.2" at 12769.7,5889 h60
  text "mm" at 12984.46,5889 h60
  text "MIN. VIA PAD SIZE:" at 11733.46,5757 h60
  text "20" at 12799.71,5757 h60
  text "MIL" at 12984.46,5757 h60
  text "0.05mm (2MIL)" at 12428.46,5615.29 h60
  text "MINIMUM ANNULAR RING" at 11404.23,5611 h60
  text "EXTERNAL" at 13136.46,5611 h60
  text "PER" at 11604.23,5493 h60
  text "IPC-D-275 CLASS 2 LEVEL C" at 11824.23,5493 h60
  text "MIL, HOLES" at 13312.46,5380.71 h60
  text "+/-" at 12920,5380 h60
  text "+/-" at 13774,5380 h60
  text "REGISTRATION TOLERANCES:" at 11404.23,5375 h60
  text "METAL" at 12604,5375 h60
  text "5" at 13180.2,5375 h60
  text "3" at 14013.2,5375 h60
  text "MIL" at 14129.46,5375 h60
  text "+/-" at 13774,5262 h60
  text "HOLE SIZE TOLERANCE (UNLESS OTHERWISE SPECIFIED):" at 11404.23,5257 h60
  text "3" at 14013.2,5257 h60
  text "MIL" at 14129.46,5257 h60
  text "MATERIAL:" at 11329.46,5047.54 h60
  text "FR-4 High Tg" at 12315.9,4907.21 h60
  text "FR-408" at 11750.46,4898.64 h60
  text "OTHER" at 13238.46,4898.64 h60
  text "X" at 12161,4895 h60
  text "62 MIL (1.6mm) +/-10%" at 12070.56,4735.92 h60
  text "THICKNESS:" at 11404.23,4731.64 h60
  text "X" at 11942.4,4731.64 h60
  text "OTHER" at 13355.46,4731.64 h60
  text "TOLERANCE:" at 11404.23,4573.64 h60
  text "X" at 12243.53,4573.64 h60
  text "ANSI IPC-6012 TYPE 3 CLASS 2" at 12430.48,4573.64 h60
  text "OTHER +/-" at 12430.46,4417.64 h60
  text "BOW & TWIST:" at 11404.23,4260.64 h60
  text "X" at 12243.53,4260.64 h60
  text "ANSI IPC-6012 TYPE 3 CLASS 2" at 12430.48,4260.64 h60
  text "OTHER +/-" at 12430.46,4102.13 h60
  text "DRILLING:" at 11329.46,3963.64 h60
  text "REFERENCE:" at 11404.23,3846.64 h60
  text "X" at 12052.46,3846.64 h60
  text "AS SHOWN" at 12239.46,3846.64 h60
  text "X" at 12953.46,3846.64 h60
  text "NC_DRILL FILES" at 13090.46,3846.64 h60
  text "PTH COPPER THICKNESS:" at 11404.23,3688.64 h60
  text "X" at 12534.46,3688.64 h60
  text "20-30 um" at 12671.46,3688.64 h60
  text "OTHER" at 13388.46,3688.64 h60
  text "BOARD FINISH:" at 11329.46,3529.64 h60
  text "SILKSCREEN:" at 11484.68,3411.64 h60
  text "X" at 12433.46,3411.64 h60
  text "TOP" at 12559.46,3411.64 h60
  text "X" at 12943.46,3411.64 h60
  text "BOTTOM" at 13070.46,3411.64 h60
  text "SILKSCREEN COLOR:" at 11484.68,3244.64 h60
  text "X" at 12432.42,3244.64 h60
  text "WHITE" at 12559.46,3244.64 h60
  text "OTHER" at 13070.46,3244.64 h60
  text "X" at 12563.42,3085.44 h60
  text "GREEN" at 12690.46,3085.44 h60
  text "OTHER" at 13308.46,3085.44 h60
  text "SOLDER RESIST COLOR:" at 11484.68,3074.64 h60
  text "X" at 12563.42,2915.44 h60
  text "MATTE" at 12690.46,2915.44 h60
  text "SEMI-GLOSS" at 13308,2914.8 h60
  text "IMMERSION GOLD (ENIG)" at 12390.46,2726.92 h60
  text "ENEPIG" at 13728,2723.64 h60
  text "SURFACE FINISH:" at 11329.46,2722.64 h60
  text "X" at 12203.51,2722.64 h60
  text "IMM. TIN/SILVER OR EQUIV" at 11659,2565.64 h60
  text "OTHER" at 13090.46,2565.64 h60
  text "ARRAY/PANEL:" at 11329.46,2386.64 h60
  text "CUT AND TRIM PER M1 BOARD OUTLINE" at 12390.46,2382.35 h60
  text "N.C. ROUTE" at 12390.46,2230.64 h60
  text "X" at 13069.46,2230.64 h60
  text "V. SCORE" at 13256.46,2230.64 h60
  text "CERTIFICATION:" at 11329.46,2093.64 h60
  text "MATERIALS AND WORKMANSHIP FOR ALL PCBS" at 12054.46,2093.64 h60
  text "TO MEET OR EXCEED THE REQUIREMENTS OF:" at 12054.46,1995.64 h60
  text "X" at 11680.96,1859.13 h60
  text "ANSI IPC-A-600F CLASS ->" at 11819.96,1859.13 h60
  text "X" at 13459.02,1859.13 h60
  text "2" at 13577.96,1859.14 h60
  text "1" at 13262.96,1857.64 h60
  text "3" at 13931.96,1857.64 h60
  text "ALL 9.7MIL-HOLED VIAS-IN-PADS MUST BE FILLED AND PLATED CLOSED" at 5305,1810 h60
  text "X" at 12495.02,1699.64 h60
  text "RoHS" at 12631.96,1699.64 h60
  text "OTHER" at 13276.36,1699.64 h60
  text "PER ORDER" at 13673.42,1699.64 h60
  text "ALL BOARDS MUST MEET OR EXCEED UL94-V0 REQUIREMENTS." at 11357,1534 h60
  text "PCB MUST BEAR THE UL94V-0 UL REGISTERED MATERIAL ID NUMBER" at 11357,1414 h60
  text "ADDITIONAL REQUIREMENTS:" at 11329.46,1240.64 h60
  text "MICROSECTION:" at 11404.23,1125.64 h60
  text "YES" at 12309.96,1125.64 h60
  text "REQUIRED" at 13171.46,969.49 h60
  text "BARE BOARD ELEC. TEST:" at 11404.23,966.64 h60
  text "NONE" at 12709.96,966.64 h60
  text "X" at 13044.46,966.64 h60
  text "PER ORDER" at 13763.46,966.64 h60
  text ".Layer_Name" at 577,-858.49 h60
M11 Gerber Information:
  lines w10: -292,-930.17 6308,-930.17 ; -292,-726.83 6310,-726.83 ; -292,-523.5 -292,-1133.5 3713,-1133.5 6310,-1133.5 6310,-523.5 -291.5,-523.5 -291.5,-1133.5 1284,-1133.5 ; 2173,-1133.5 2173,-523.5 ; 3440,-726.83 3440,-523.5 ; 4280,-726.83 4280,-523.5 ; 4902,-1140 4902,-937.17
  text "ALL ARTWORK VIEWED FROM TOP SIDE" at -228.5,-655.67 h60
  text "BOARD #:" at 2248,-655.67 h60
  text ".PRJ_Number" at 2793.5,-655.67 h60
  text "REV:" at 3638,-655.67 h60
  text ".PCB_Rev" at 3929.5,-655.67 h60
  text "SVN REV:" at 4476,-655.67 h60
  text ".VersionControl_RevNumber" at 4982,-655.67 h60
  text "LAYER NAME =" at -228.5,-858.49 h60
  text "TID #:" at 2248,-859 h60
  text ".TID" at 2793.5,-859 h60
  text "PLOT NAME =" at -228.5,-1064.34 h60
  text ".plot_File_Name" at 577,-1064.34 h60
  text "GENERATED    :" at 2250,-1064.34 h60
  text ".Print_Date" at 3119.5,-1064.34 h60
  text ".Print_Time" at 3848.5,-1064.34 h60
  text "TEXAS INSTRUMENTS" at 5113,-1064.34 h60
M12 Stackup:
  drawing of 503 lines, arcs and shapes, not listed
  text "Layer" at 6727.5,7807.5 h60
  text "Name" at 7137.41,7807.5 h60
  text "Material" at 8077.15,7807.5 h60
  text "Thickness" at 8936.92,7807.5 h60
  text "Constant" at 9586.76,7807.5 h60
  text "Board Layer Stack" at 10156.62,7807.5 h60
  text "1" at 6727.5,7687.5 h60
  text "Top Overlay" at 7137.41,7687.5 h60
  text "2" at 6727.5,7567.5 h60
  text "Top Solder" at 7137.41,7567.5 h60
  text "Solder Resist" at 8077.15,7567.5 h60
  text "0.40mil" at 8936.92,7567.5 h60
  text "3.5" at 9586.76,7567.5 h60
  text "3" at 6727.5,7447.5 h60
  text "Top Layer" at 7137.41,7447.5 h60
  text "Copper" at 8077.15,7447.5 h60
  text "2.10mil" at 8936.92,7447.5 h60
  text "4" at 6727.5,7327.5 h60
  text "Dielectric1" at 7137.41,7327.5 h60
  text "FR-4 High TG" at 8077.15,7327.5 h60
  text "6.00mil" at 8936.92,7327.5 h60
  text "4.8" at 9586.76,7327.5 h60
  text "5" at 6727.5,7207.5 h60
  text "Signal Layer 1" at 7137.41,7207.5 h60
  text "Copper" at 8077.15,7207.5 h60
  text "2.80mil" at 8936.92,7207.5 h60
  text "6" at 6727.5,7087.5 h60
  text "Dielectric 3" at 7137.41,7087.5 h60
  text "FR-4 High TG" at 8077.15,7087.5 h60
  text "6.00mil" at 8936.92,7087.5 h60
  text "4.8" at 9586.76,7087.5 h60
  text "7" at 6727.5,6967.5 h60
  text "Signal Layer 2" at 7137.41,6967.5 h60
  text "Copper" at 8077.15,6967.5 h60
  text "2.80mil" at 8936.92,6967.5 h60
  text "8" at 6727.5,6847.5 h60
  text "Dielectric 4" at 7137.41,6847.5 h60
  text "FR-4 High TG" at 8077.15,6847.5 h60
  text "6.00mil" at 8936.92,6847.5 h60
  text "4.8" at 9586.76,6847.5 h60
  text "9" at 6727.5,6727.5 h60
  text "Signal Layer 3" at 7137.41,6727.5 h60
  text "Copper" at 8077.15,6727.5 h60
  text "2.80mil" at 8936.92,6727.5 h60
  text "10" at 6727.5,6607.5 h60
  text "Dielectric 5" at 7137.41,6607.5 h60
  text "FR-4 High TG" at 8077.15,6607.5 h60
  text "6.00mil" at 8936.92,6607.5 h60
  text "4.8" at 9586.76,6607.5 h60
  text "11" at 6727.5,6487.5 h60
  text "Signal Layer 4" at 7137.41,6487.5 h60
  text "Copper" at 8077.15,6487.5 h60
  text "2.80mil" at 8936.92,6487.5 h60
  text "12" at 6727.5,6367.5 h60
  text "Dielectric 6" at 7137.41,6367.5 h60
  text "FR-4 High TG" at 8077.15,6367.5 h60
  text "6.00mil" at 8936.92,6367.5 h60
  text "4.8" at 9586.76,6367.5 h60
  text "13" at 6727.5,6247.5 h60
  text "Signal Layer 5" at 7137.41,6247.5 h60
  text "Copper" at 8077.15,6247.5 h60
  text "2.80mil" at 8936.92,6247.5 h60
  text "14" at 6727.5,6127.5 h60
  text "Dielectric 7" at 7137.41,6127.5 h60
  text "FR-4 High TG" at 8077.15,6127.5 h60
  text "6.00mil" at 8936.92,6127.5 h60
  text "4.8" at 9586.76,6127.5 h60
  text "15" at 6727.5,6007.5 h60
  text "Signal Layer 6" at 7137.41,6007.5 h60
  text "Copper" at 8077.15,6007.5 h60
  text "2.80mil" at 8936.92,6007.5 h60
  text "16" at 6727.5,5887.5 h60
  text "Dielectric 2" at 7137.41,5887.5 h60
  text "FR-4 High TG" at 8077.15,5887.5 h60
  text "6.00mil" at 8936.92,5887.5 h60
  text "4.8" at 9586.76,5887.5 h60
  text "17" at 6727.5,5767.5 h60
  text "Bottom Layer" at 7137.41,5767.5 h60
  text "Copper" at 8077.15,5767.5 h60
  text "2.10mil" at 8936.92,5767.5 h60
  text "18" at 6727.5,5647.5 h60
  text "Bottom Solder" at 7137.41,5647.5 h60
  text "Solder Resist" at 8077.15,5647.5 h60
  text "0.40mil" at 8936.92,5647.5 h60
  text "3.5" at 9586.76,5647.5 h60
  text "19" at 6727.5,5527.5 h60
  text "Bottom Overlay" at 7137.41,5527.5 h60
  text ".Layer_Name" at 577,-858.49 h60
M13 Component Bodies Top:
  text ".Layer_Name" at 577,-858.49 h60
M14 Component Bodies Bottom:
  text ".Layer_Name" at 577,-858.49 h60
M15 Courtyards Top:
  text ".Layer_Name" at 577,-858.49 h60
M16 Courtyards Bottom:
  text ".Layer_Name" at 577,-858.49 h60
Drill Drawing:
  circle w10: c5363.72,3141.96 r16.58
  circle w10: c5363.72,3141.96 r27.63
  circle w10: c5363.72,2893.32 r27.63
  lines w10: 5336.09,2119.78 5363.72,2133.59 5391.34,2119.78 5377.53,2147.4 5391.34,2175.03 5363.72,2161.22 5336.09,2175.03 5349.9,2147.4 5336.09,2119.78 ; 5336.09,2257.91 5349.9,2257.91 5363.72,2244.1 5377.53,2257.91 5391.34,2257.91 5377.53,2271.72 5391.34,2285.54 5377.53,2285.54 5363.72,2299.35 5349.9,2285.54 5336.09,2285.54 5349.9,2271.72 5336.09,2257.91 ; 5336.09,2423.67 5391.34,2423.67 5363.72,2368.42 5336.09,2423.67 ; 5336.09,2492.74 5391.34,2492.74 5391.34,2547.99 5336.09,2547.99 5336.09,2492.74 ; 5336.09,2630.87 5349.9,2630.87 5349.9,2617.06 5377.53,2617.06 5377.53,2630.87 5391.34,2630.87 5391.34,2658.5 5377.53,2658.5 5377.53,2672.31 5349.9,2672.31 5349.9,2658.5 5336.09,2658.5 5336.09,2630.87 ; 5336.09,2769 5363.72,2741.38 5391.34,2769 5363.72,2796.63 5336.09,2769 ; 5336.09,2990.02 5391.34,2990.02 5391.34,3045.27 5336.09,3045.27 5336.09,2990.02 ; 5336.09,3238.66 5336.09,3252.47 5349.9,3266.28 5336.09,3280.1 5336.09,3293.91 5349.9,3293.91 5363.72,3280.1 5377.53,3293.91 5391.34,3293.91 5391.34,3280.1 5377.53,3266.28 5391.34,3252.47 5391.34,3238.66 5377.53,3238.66 5363.72,3252.47 5349.9,3238.66 5336.09,3238.66 ; 5347.14,3001.07 5380.29,3001.07 5380.29,3034.22 5347.14,3034.22 5347.14,3001.07
  lines w12: 5286,2082.48 8517.49,2082.48 ; 5286,3325.68 8517.49,3325.68 ; 5623.86,1958.16 5623.86,3450 ; 5955.86,1958.16 5955.86,3450 ; 6592.43,1958.16 6592.43,3450 ; 6851.57,1958.16 6851.57,3450 ; 7226.72,1958.16 7226.72,3450 ; 7951.05,1958.16 7951.05,3450 ; 5286,1958.16 8517.49,1958.16 8517.49,3450 5286,3450 5286,1958.16
  text "Symbol" at 5360.59,3362.98 h72
  text "Quantity" at 5661.16,3362.98 h72
  text "Finished Hole Size" at 5993.16,3362.98 h72
  text "Plated" at 6629.72,3362.98 h72
  text "Hole Type" at 6888.86,3362.98 h72
  text "Drill Layer Pair" at 7264.02,3362.98 h72
  text "Hole Tolerance" at 7988.35,3362.98 h72
  text "112" at 5661.16,3238.66 h60
  text "7.87mil (0.200mm)" at 5993.16,3238.66 h60
  text "PTH" at 6629.72,3238.66 h60
  text "Round" at 6888.86,3238.66 h60
  text "Top Layer - Bottom Layer" at 7264.02,3238.66 h60
  text "144" at 5661.16,3114.34 h60
  text "9.70mil (0.246mm)" at 5993.16,3114.34 h60
  text "PTH" at 6629.72,3114.34 h60
  text "Round" at 6888.86,3114.34 h60
  text "Top Layer - Bottom Layer" at 7264.02,3114.34 h60
  text "216" at 5661.16,2990.02 h60
  text "10.00mil (0.254mm)" at 5993.16,2990.02 h60
  text "PTH" at 6629.72,2990.02 h60
  text "Round" at 6888.86,2990.02 h60
  text "Top Layer - Bottom Layer" at 7264.02,2990.02 h60
  text "211" at 5661.16,2865.7 h60
  text "13.00mil (0.330mm)" at 5993.16,2865.7 h60
  text "PTH" at 6629.72,2865.7 h60
  text "Round" at 6888.86,2865.7 h60
  text "Top Layer - Bottom Layer" at 7264.02,2865.7 h60
  text "344" at 5661.16,2741.38 h60
  text "16.00mil (0.406mm)" at 5993.16,2741.38 h60
  text "PTH" at 6629.72,2741.38 h60
  text "Round" at 6888.86,2741.38 h60
  text "Top Layer - Bottom Layer" at 7264.02,2741.38 h60
  text "6" at 5661.16,2617.06 h60
  text "35.43mil (0.900mm)" at 5993.16,2617.06 h60
  text "PTH" at 6629.72,2617.06 h60
  text "Round" at 6888.86,2617.06 h60
  text "Top Layer - Bottom Layer" at 7264.02,2617.06 h60
  text "61" at 5661.16,2492.74 h60
  text "40.00mil (1.016mm)" at 5993.16,2492.74 h60
  text "PTH" at 6629.72,2492.74 h60
  text "Round" at 6888.86,2492.74 h60
  text "Top Layer - Bottom Layer" at 7264.02,2492.74 h60
  text "4" at 5661.16,2368.42 h60
  text "50.00mil (1.270mm)" at 5993.16,2368.42 h60
  text "PTH" at 6629.72,2368.42 h60
  text "Round" at 6888.86,2368.42 h60
  text "Top Layer - Bottom Layer" at 7264.02,2368.42 h60
  text "4" at 5661.16,2244.1 h60
  text "188.00mil (4.775mm)" at 5993.16,2244.1 h60
  text "PTH" at 6629.72,2244.1 h60
  text "Round" at 6888.86,2244.1 h60
  text "Top Layer - Bottom Layer" at 7264.02,2244.1 h60
  text "4" at 5661.16,2119.78 h60
  text "254.00mil (6.452mm)" at 5993.16,2119.78 h60
  text "PTH" at 6629.72,2119.78 h60
  text "Round" at 6888.86,2119.78 h60
  text "Top Layer - Bottom Layer" at 7264.02,2119.78 h60
  text "1106 Total" at 5661.16,1995.46 h60
  text "ALL 9.7MIL-HOLED VIAS-IN-PADS MUST BE FILLED AND PLATED CLOSED" at 5304.23,1811 h60
  text ".Layer_Name" at 577,-858.49 h60
M17 Embedded Cavity:
  text ".Layer_Name" at 577,-858.49 h60
M18 Embedded Assembly:
  text ".Layer_Name" at 577,-858.49 h60
M19 Embedded Keepout:
  text ".Layer_Name" at 577,-858.49 h60

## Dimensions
0,-400 to 1000,-400 on M2 Board Dimensions
0,0 to 0,6000 on M2 Board Dimensions
0,0 to 4000,0 on M2 Board Dimensions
